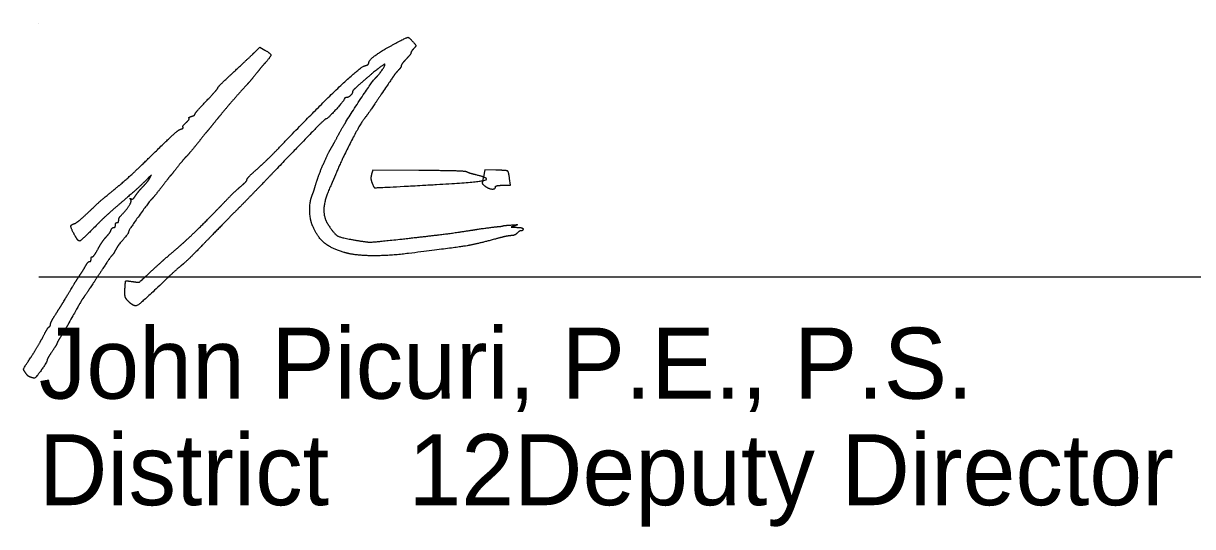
# Model space of a CAD drawing. Extents: x -8.3 to 34, y 0 to 22.
# Drawn here: x 24.409 to 26.714, y 4.327 to 5.32 of the extents above; entities that cross this region are included whole.
import ezdxf

# ---------------------------------------------------------------- set-up
doc = ezdxf.new("R2010")
doc.units = 0
doc.layers.add('SH_Data', color=7, linetype='Continuous')
doc.layers.add('SH_Text', color=7, linetype='Continuous')

msp = doc.modelspace()

# ---------------------------------------------------------------- linework, layer by layer
at = {"layer": 'SH_Data'}
for p, q in [((24.4399, 5.3197), (24.4399, 5.3197)), ((24.4399, 4.8197), (27.9399, 4.8197))]:
    msp.add_line(p, q, dxfattribs=at)
at = {"layer": 'SH_Text'}
for p, q in [((25.0963, 5.0057), (25.0963, 5.0057)), ((25.3192, 4.9988), (25.3192, 4.9988)), ((24.6148, 4.7733), (24.6148, 4.7733)), ((24.4239, 4.6218), (24.4239, 4.6218))]:
    msp.add_line(p, q, dxfattribs=at)
for points in [[(24.8647, 5.2622), (24.8756, 5.2729), (24.8852, 5.2671)], [(25.189, 5.0296), (25.0984, 5.0301), (25.0957, 5.0221)], [(25.3408, 5.0303), (25.319, 5.0308), (25.3161, 5.0171)], [(24.6587, 5.0148), (24.6621, 5.0212), (24.6557, 5.0148)], [(25.3545, 5.0004), (25.3693, 5.0004), (25.3676, 5.0135)]]:
    msp.add_lwpolyline(points, dxfattribs=at)
for points in [[(25.0901, 5.2417), (25.0901, 5.247), (25.1161, 5.2661), (25.1422, 5.2801)], [(25.1422, 5.2801), (25.1648, 5.2921), (25.1699, 5.2922), (25.1796, 5.2805)], [(25.1796, 5.2805), (25.1831, 5.2764), (25.1829, 5.2745), (25.1785, 5.2697)], [(24.8232, 5.223), (24.8401, 5.2388), (24.8588, 5.2564), (24.8647, 5.2622)], [(24.8852, 5.2671), (24.8968, 5.2603), (24.8974, 5.2543), (24.8876, 5.2436)], [(25.1733, 5.2616), (25.1733, 5.2603), (25.169, 5.2547), (25.1637, 5.2491)], [(25.1785, 5.2697), (25.1756, 5.2665), (25.1733, 5.2629), (25.1733, 5.2616)], [(24.8876, 5.2436), (24.8836, 5.2392), (24.8746, 5.2285), (24.8676, 5.2198)], [(24.9108, 5.0719), (24.9811, 5.1455), (25.0731, 5.2337), (25.0819, 5.2359)], [(25.1221, 5.2386), (25.1221, 5.2408), (25.097, 5.2214), (25.0736, 5.201)], [(25.0819, 5.2359), (25.0864, 5.237), (25.0901, 5.2396), (25.0901, 5.2417)], [(25.1046, 5.2132), (25.1092, 5.2173), (25.1221, 5.236), (25.1221, 5.2386)], [(25.1541, 5.2362), (25.1541, 5.2348), (25.1523, 5.2316), (25.1501, 5.2291)], [(25.1637, 5.2491), (25.1584, 5.2434), (25.1541, 5.2376), (25.1541, 5.2362)], [(24.7925, 5.1923), (24.7925, 5.1935), (24.8063, 5.2073), (24.8232, 5.223)], [(24.8676, 5.2198), (24.8606, 5.211), (24.8527, 5.2016), (24.8501, 5.1988)], [(25.0308, 5.1007), (25.0427, 5.123), (25.0981, 5.2075), (25.1046, 5.2132)], [(25.1501, 5.2291), (25.142, 5.2201), (25.1388, 5.2156), (25.1124, 5.1764)], [(24.7701, 5.1668), (24.7824, 5.1797), (24.7925, 5.1912), (24.7925, 5.1923)], [(24.8501, 5.1988), (24.8387, 5.1867), (24.8079, 5.1513), (24.7972, 5.138)], [(25.0581, 5.185), (25.0581, 5.1812), (25.0495, 5.1732), (25.0455, 5.1732)], [(25.0736, 5.201), (25.0651, 5.1936), (25.0581, 5.1864), (25.0581, 5.185)], [(24.7477, 5.1409), (24.7477, 5.1423), (24.7578, 5.1539), (24.7701, 5.1668)], [(25.042, 5.1708), (25.0419, 5.1679), (25.0088, 5.1316), (25.0063, 5.1316)], [(25.0455, 5.1732), (25.0436, 5.1732), (25.042, 5.1721), (25.042, 5.1708)], [(25.1124, 5.1764), (25.0976, 5.1544), (25.0847, 5.1357), (25.0837, 5.1348)], [(24.741, 5.1363), (24.7447, 5.1375), (24.7477, 5.1396), (24.7477, 5.1409)], [(24.724, 5.1148), (24.723, 5.1158), (24.7257, 5.1198), (24.7299, 5.1238)], [(24.7299, 5.1238), (24.7342, 5.1277), (24.7369, 5.1317), (24.736, 5.1326)], [(24.736, 5.1326), (24.7351, 5.1335), (24.7374, 5.1352), (24.741, 5.1363)], [(24.7972, 5.138), (24.7907, 5.1301), (24.7808, 5.1179), (24.775, 5.1108)], [(25.0063, 5.1316), (25.0043, 5.1316), (24.9736, 5.1005), (24.9039, 5.0278)], [(25.0837, 5.1348), (25.0769, 5.1283), (25.0373, 5.0524), (25.0245, 5.0212)], [(24.6828, 5.0795), (24.6993, 5.0957), (24.7158, 5.1098), (24.7193, 5.111)], [(24.7193, 5.111), (24.7229, 5.1121), (24.725, 5.1138), (24.724, 5.1148)], [(24.775, 5.1108), (24.7693, 5.1038), (24.7576, 5.0894), (24.7491, 5.0788)], [(25.0162, 5.074), (25.0178, 5.0767), (25.0244, 5.0887), (25.0308, 5.1007)], [(24.5902, 4.9933), (24.6076, 5.0075), (24.6416, 5.0391), (24.6828, 5.0795)], [(24.7491, 5.0788), (24.7406, 5.0683), (24.732, 5.0582), (24.73, 5.0564)], [(24.87, 5.0325), (24.8809, 5.0421), (24.8993, 5.0599), (24.9108, 5.0719)], [(24.9861, 5.0036), (24.991, 5.02), (25.0095, 5.063), (25.0162, 5.074)], [(24.73, 5.0564), (24.728, 5.0547), (24.7207, 5.046), (24.7138, 5.0372)], [(24.7138, 5.0372), (24.7069, 5.0284), (24.7005, 5.0205), (24.6995, 5.0196)], [(24.9039, 5.0278), (24.8787, 5.0015), (24.843, 4.9647), (24.8245, 4.9459)], [(24.8501, 5.0116), (24.8501, 5.0134), (24.859, 5.0228), (24.87, 5.0325)], [(25.2833, 5.0268), (25.2813, 5.0281), (25.2389, 5.0293), (25.189, 5.0296)], [(25.3004, 5.0212), (25.293, 5.023), (25.2853, 5.0255), (25.2833, 5.0268)], [(25.3642, 5.0282), (25.3633, 5.0291), (25.3528, 5.03), (25.3408, 5.0303)], [(25.3676, 5.0135), (25.3666, 5.0207), (25.3651, 5.0273), (25.3642, 5.0282)], [(24.6557, 5.0148), (24.6439, 5.0029), (24.6214, 4.9825), (24.5973, 4.962)], [(24.6461, 4.9988), (24.6512, 5.0041), (24.6569, 5.0113), (24.6587, 5.0148)], [(24.6995, 5.0196), (24.6986, 5.0187), (24.691, 5.0091), (24.6827, 4.9982)], [(24.8384, 4.9988), (24.8448, 5.0041), (24.8501, 5.0098), (24.8501, 5.0116)], [(24.9778, 4.9787), (24.9794, 4.9827), (24.9832, 4.9939), (24.9861, 5.0036)], [(25.0163, 5.002), (25.0034, 4.9745), (25.0002, 4.9385), (25.0092, 4.9243)], [(25.0245, 5.0212), (25.0216, 5.0142), (25.0179, 5.0055), (25.0163, 5.002)], [(25.0957, 5.0221), (25.0942, 5.0175), (25.0944, 5.0106), (25.0963, 5.0057)], [(25.0963, 5.0057), (25.1001, 4.9956), (25.1032, 4.9954), (25.1957, 5.0004)], [(25.1957, 5.0004), (25.2973, 5.0059), (25.3342, 5.0132), (25.3004, 5.0212)], [(25.3161, 5.0171), (25.3135, 5.0053), (25.314, 5.0028), (25.3192, 4.9988)], [(25.3397, 4.9972), (25.3397, 4.999), (25.3463, 5.0004), (25.3545, 5.0004)], [(24.5372, 4.9469), (24.5585, 4.9671), (24.5642, 4.9721), (24.5902, 4.9933)], [(24.622, 4.9737), (24.6239, 4.9726), (24.6279, 4.9756), (24.631, 4.9805)], [(24.631, 4.9805), (24.6342, 4.9853), (24.6409, 4.9935), (24.6461, 4.9988)], [(24.6827, 4.9982), (24.6744, 4.9873), (24.6657, 4.9765), (24.6634, 4.9742)], [(24.8088, 4.9704), (24.8186, 4.9808), (24.832, 4.9935), (24.8384, 4.9988)], [(24.9796, 4.92), (24.9743, 4.932), (24.9733, 4.9673), (24.9778, 4.9787)], [(25.3192, 4.9988), (25.3262, 4.9935), (25.3397, 4.9925), (25.3397, 4.9972)], [(24.5973, 4.962), (24.5841, 4.9508), (24.5652, 4.9335), (24.5554, 4.9236)], [(24.6014, 4.9402), (24.613, 4.9521), (24.6232, 4.9686), (24.6211, 4.972)], [(24.6634, 4.9742), (24.6567, 4.9675), (24.6165, 4.9111), (24.6165, 4.9085)], [(24.6211, 4.972), (24.6196, 4.9743), (24.62, 4.975), (24.622, 4.9737)], [(24.7245, 4.8868), (24.7372, 4.8979), (24.7828, 4.9432), (24.8088, 4.9704)], [(24.5103, 4.925), (24.5135, 4.9261), (24.5256, 4.9359), (24.5372, 4.9469)], [(24.5941, 4.9268), (24.5958, 4.9268), (24.5973, 4.9289), (24.5973, 4.9314)], [(24.5973, 4.9314), (24.5973, 4.9339), (24.5991, 4.9379), (24.6014, 4.9402)], [(24.8245, 4.9459), (24.806, 4.9272), (24.7776, 4.8982), (24.7613, 4.8814)], [(24.5094, 4.9043), (24.5029, 4.9167), (24.5032, 4.9228), (24.5103, 4.925)], [(24.5554, 4.9236), (24.5243, 4.8922), (24.5172, 4.8892), (24.5094, 4.9043)], [(24.5727, 4.8987), (24.5769, 4.9032), (24.5812, 4.9092), (24.5823, 4.9121)], [(24.5823, 4.9121), (24.5834, 4.9149), (24.5858, 4.9172), (24.5876, 4.9172)], [(24.5876, 4.9172), (24.5894, 4.9172), (24.5909, 4.9194), (24.5909, 4.922)], [(24.5909, 4.922), (24.5909, 4.9247), (24.5923, 4.9268), (24.5941, 4.9268)], [(24.6165, 4.9085), (24.6165, 4.9064), (24.6131, 4.9018), (24.5978, 4.8834)], [(25.0419, 4.8679), (25.0162, 4.8755), (24.9892, 4.8981), (24.9796, 4.92)], [(25.0092, 4.9243), (25.022, 4.9043), (25.0353, 4.8969), (25.0679, 4.8915)], [(25.1557, 4.8945), (25.2117, 4.9007), (25.2617, 4.907), (25.2933, 4.912)], [(25.2933, 4.912), (25.3061, 4.9141), (25.3361, 4.9181), (25.3461, 4.9191)], [(25.3461, 4.9191), (25.3505, 4.9195), (25.3541, 4.9201), (25.3541, 4.9204)], [(25.3541, 4.9204), (25.3541, 4.9207), (25.3613, 4.9215), (25.3701, 4.9221)], [(25.3701, 4.9221), (25.3818, 4.923), (25.3839, 4.9225), (25.3781, 4.9206)], [(25.3781, 4.9206), (25.3708, 4.9181), (25.3712, 4.9178), (25.3821, 4.9175)], [(25.3821, 4.9175), (25.3887, 4.9174), (25.3941, 4.9158), (25.3941, 4.914)], [(25.3906, 4.9108), (25.3888, 4.9108), (25.3851, 4.9087), (25.3824, 4.906)], [(25.3941, 4.914), (25.3941, 4.9123), (25.3925, 4.9108), (25.3906, 4.9108)], [(24.5566, 4.875), (24.5612, 4.8835), (24.5685, 4.8941), (24.5727, 4.8987)], [(24.6946, 4.8608), (24.705, 4.8698), (24.7185, 4.8815), (24.7245, 4.8868)], [(25.0679, 4.8915), (25.0886, 4.8881), (25.1, 4.8885), (25.1557, 4.8945)], [(25.3397, 4.8945), (25.302, 4.8842), (25.2628, 4.8777), (25.1685, 4.866)], [(25.3706, 4.9011), (25.3668, 4.9011), (25.3529, 4.8981), (25.3397, 4.8945)], [(25.3824, 4.906), (25.3798, 4.9034), (25.3745, 4.9012), (25.3706, 4.9011)], [(24.5456, 4.8596), (24.547, 4.8596), (24.552, 4.8665), (24.5566, 4.875)], [(24.5846, 4.8628), (24.5834, 4.8619), (24.5706, 4.8432), (24.5562, 4.8212)], [(24.5908, 4.8722), (24.5886, 4.8679), (24.5858, 4.8637), (24.5846, 4.8628)], [(24.5978, 4.8834), (24.5962, 4.8816), (24.5931, 4.8765), (24.5908, 4.8722)], [(24.7613, 4.8814), (24.7451, 4.8646), (24.7273, 4.8474), (24.722, 4.8432)], [(25.1685, 4.866), (25.1277, 4.861), (25.0621, 4.862), (25.0419, 4.8679)], [(24.5202, 4.8225), (24.5248, 4.8293), (24.5304, 4.8383), (24.5327, 4.8425)], [(24.5327, 4.8425), (24.5349, 4.8466), (24.5382, 4.85), (24.5399, 4.85)], [(24.5399, 4.85), (24.5415, 4.85), (24.5429, 4.8522), (24.5429, 4.8548)], [(24.5429, 4.8548), (24.5429, 4.8575), (24.5441, 4.8596), (24.5456, 4.8596)], [(24.6565, 4.8265), (24.667, 4.8363), (24.6842, 4.8518), (24.6946, 4.8608)], [(24.722, 4.8432), (24.7166, 4.839), (24.7018, 4.8257), (24.6891, 4.8135)], [(24.4883, 4.7703), (24.5053, 4.799), (24.513, 4.8115), (24.5202, 4.8225)], [(24.5562, 4.8212), (24.5418, 4.7992), (24.5287, 4.7797), (24.5272, 4.7778)], [(24.6257, 4.8105), (24.6364, 4.8087), (24.6388, 4.81), (24.6565, 4.8265)], [(24.6148, 4.7733), (24.611, 4.7775), (24.6092, 4.784), (24.6095, 4.7927)], [(24.6095, 4.7927), (24.6102, 4.8105), (24.6122, 4.8126), (24.6257, 4.8105)], [(24.6891, 4.8135), (24.6415, 4.7677), (24.627, 4.7599), (24.6148, 4.7733)], [(24.4733, 4.7464), (24.479, 4.7553), (24.4857, 4.7661), (24.4883, 4.7703)], [(24.5272, 4.7778), (24.5247, 4.7747), (24.5205, 4.7673), (24.4992, 4.7292)], [(24.4629, 4.7264), (24.4629, 4.7285), (24.4676, 4.7375), (24.4733, 4.7464)], [(24.4603, 4.7215), (24.4617, 4.7221), (24.4629, 4.7243), (24.4629, 4.7264)], [(24.4992, 4.7292), (24.4945, 4.7209), (24.4873, 4.7087), (24.4832, 4.7021)], [(24.4234, 4.66), (24.4314, 4.6721), (24.4424, 4.6907), (24.4479, 4.7012)], [(24.4479, 4.7012), (24.4533, 4.7118), (24.4589, 4.7209), (24.4603, 4.7215)], [(24.4832, 4.7021), (24.479, 4.6955), (24.4757, 4.6895), (24.4757, 4.6886)], [(24.4757, 4.6886), (24.4757, 4.6878), (24.4714, 4.6807), (24.4661, 4.6729)], [(24.4138, 4.6305), (24.4092, 4.6375), (24.4098, 4.6392), (24.4234, 4.66)], [(24.4565, 4.6562), (24.4565, 4.6526), (24.4334, 4.6196), (24.4311, 4.62)], [(24.4661, 4.6729), (24.4608, 4.6651), (24.4565, 4.6576), (24.4565, 4.6562)], [(24.4239, 4.6218), (24.421, 4.6226), (24.4164, 4.6265), (24.4138, 4.6305)], [(24.4311, 4.62), (24.4301, 4.6202), (24.4269, 4.621), (24.4239, 4.6218)]]:
    msp.add_open_spline(points, degree=2, dxfattribs=at)

# ---------------------------------------------------------------- texts
for s, p in [('John Picuri, P.E., P.S.', (24.4399, 4.5797)), ('District       Deputy Director', (24.4399, 4.3697)), ('              12', (24.4399, 4.3697))]:
    msp.add_text(s, height=0.14, dxfattribs=at).set_placement(p)

doc.saveas('drawing.dxf')
